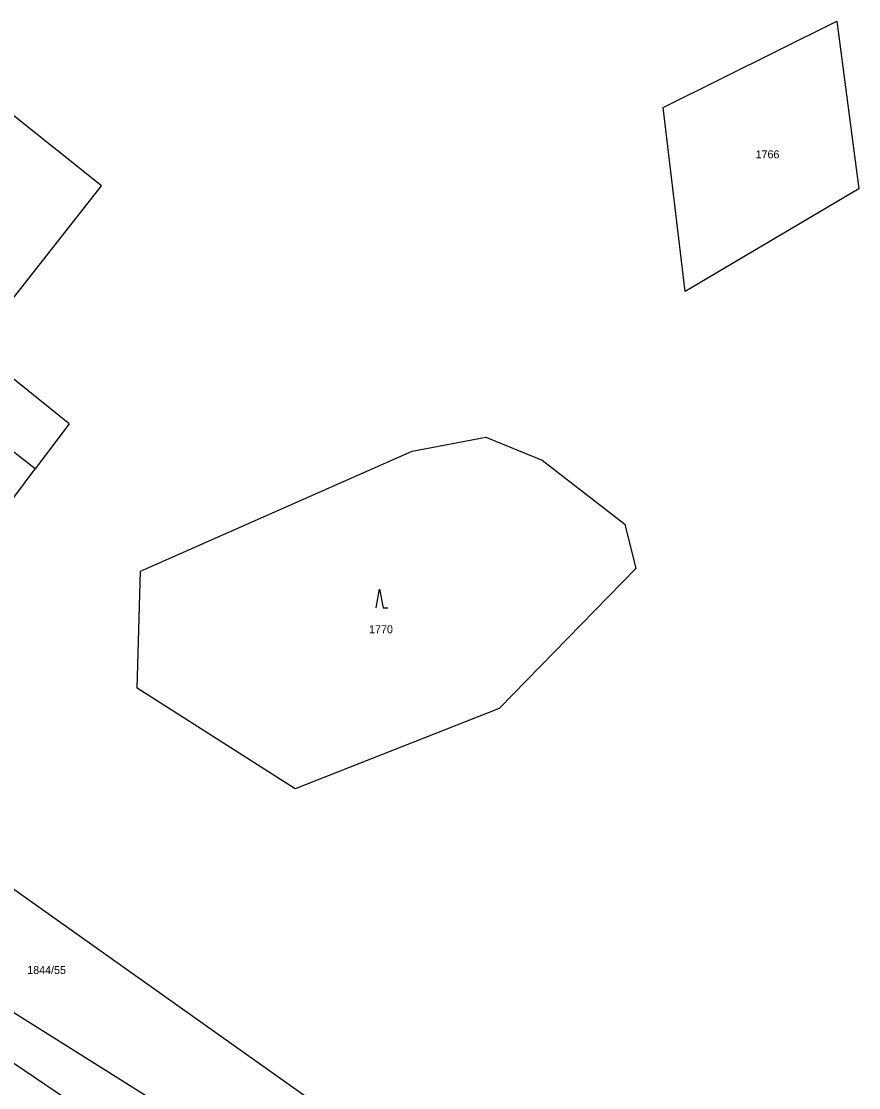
# Model space of a CAD drawing. Extents: x -747792 to -745414, y -1093712 to -1091463.
# Drawn here: x -746861.7 to -746772.8, y -1092335.2 to -1092221.9 of the extents above; entities that cross this region are included whole.
import ezdxf

# ---------------------------------------------------------------- set-up
doc = ezdxf.new("R2010")
doc.units = 0
for name, color, linetype in [('Pracovní_bod JDTM STC_VC', 7, 'Continuous'), ('Pracovní_bod JDTM STC_VC - číslo', 7, 'Continuous'), ('Pracovní_bod NN - výška', 7, 'Continuous')]:
    doc.layers.add(name, color=color, linetype=linetype)

msp = doc.modelspace()

# ---------------------------------------------------------------- linework, layer by layer
at = {"layer": 'Pracovní_bod JDTM STC_VC - číslo'}
msp.add_lwpolyline([(-746824.08, -1092284.23), (-746823.7, -1092282.23), (-746823.33, -1092284.23), (-746822.83, -1092284.23)], dxfattribs=at)
at = {"layer": 'Pracovní_bod NN - výška'}
for points in [[(-746793.59, -1092231.09), (-746775.16, -1092221.95)], [(-746775.16, -1092221.95), (-746772.85, -1092239.73)], [(-746791.26, -1092250.65), (-746793.59, -1092231.09)], [(-746853.22, -1092239.43), (-746862.87, -1092231.69)], [(-746866.75, -1092256.58), (-746853.22, -1092239.43)], [(-746772.85, -1092239.73), (-746791.26, -1092250.65)], [(-746856.67, -1092264.69), (-746866.75, -1092256.58)], [(-746860.28, -1092269.48), (-746871.51, -1092260.68)], [(-746856.67, -1092264.69), (-746860.28, -1092269.48)], [(-746820.26, -1092267.59), (-746812.43, -1092266.11)], [(-746812.43, -1092266.11), (-746806.46, -1092268.56)], [(-746849.1, -1092280.34), (-746820.26, -1092267.59)], [(-746806.46, -1092268.56), (-746797.69, -1092275.33)], [(-746882.31, -1092299.06), (-746860.28, -1092269.48)], [(-746797.69, -1092275.33), (-746796.51, -1092280.05)], [(-746849.44, -1092292.76), (-746849.1, -1092280.34)], [(-746796.51, -1092280.05), (-746811.03, -1092294.91)], [(-746832.67, -1092303.43), (-746849.44, -1092292.76)], [(-746811.03, -1092294.91), (-746832.67, -1092303.43)], [(-746863.04, -1092313.75), (-746801.85, -1092357.16)], [(-746879.52, -1092316.53), (-746809.3, -1092360.63)], [(-746812.98, -1092366.18), (-746863.74, -1092331.79)]]:
    msp.add_lwpolyline(points, dxfattribs=at)

# ---------------------------------------------------------------- texts
at = {"layer": 'Pracovní_bod JDTM STC_VC'}
for s, p in [('1766', (-746783.79, -1092236.5)), ('1770', (-746824.82, -1092286.93)), ('1844/55', (-746861.11, -1092323.11))]:
    msp.add_text(s, height=0.85, dxfattribs=at).set_placement(p)

doc.saveas('drawing.dxf')
